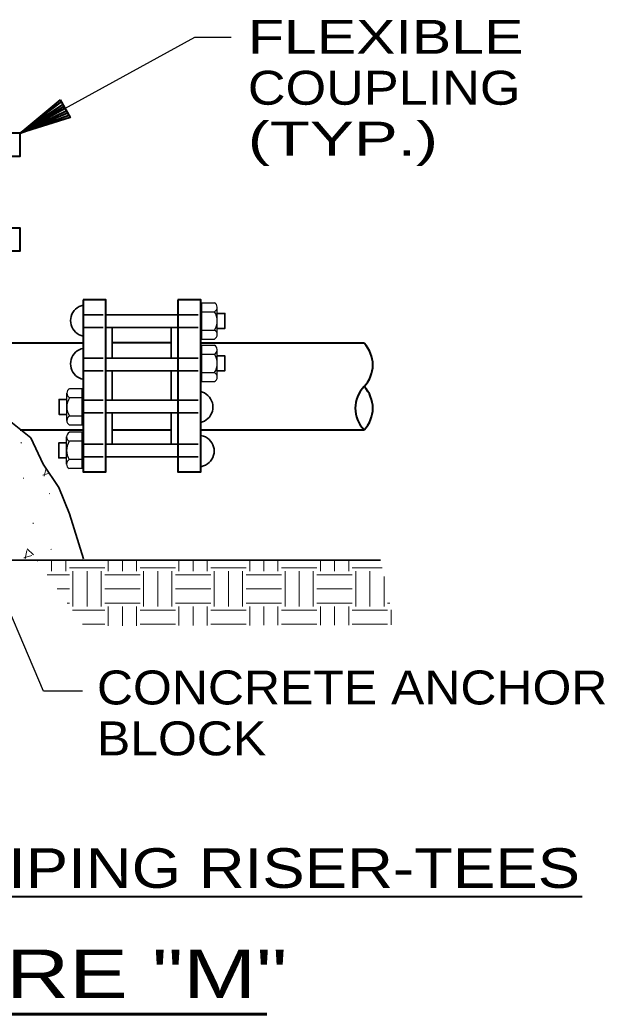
# Model space of a CAD drawing. Extents: x 55 to 190, y 198 to 264.
# Drawn here: x 96.19 to 100.57, y 222.57 to 230.01 of the extents above; entities that cross this region are included whole.
import ezdxf
from ezdxf.enums import TextEntityAlignment as Align

# ---------------------------------------------------------------- set-up
doc = ezdxf.new("R2010")
doc.units = 0
doc.header["$LTSCALE"] = 0.1
doc.linetypes.add('SHORT_DASHED', pattern=[2.7, 1.5, -1.2])
doc.layers.add('2', color=7, linetype='Continuous', lineweight=40)

msp = doc.modelspace()

# ---------------------------------------------------------------- linework, layer by layer
at = {"layer": '2'}
for p, q in [((96.1973, 229.1653), (96.5053, 229.3992)), ((96.1973, 229.1653), (96.5158, 229.3807)), ((96.1973, 229.1653), (96.5235, 229.3656)), ((96.5325, 229.35), (96.1973, 229.1653)), ((96.1973, 229.1653), (96.5415, 229.3331)), ((96.1973, 229.1653), (96.5595, 229.3003)), ((95.8777, 227.5972), (96.6672, 227.5972)), ((97.3257, 227.5977), (96.8852, 227.5977)), ((97.5483, 227.5972), (98.7696, 227.5972)), ((96.197, 226.9465), (96.6672, 226.9465)), ((96.8852, 226.9465), (97.3257, 226.9465)), ((97.5483, 226.9463), (98.7696, 226.9463)), ((91.6756, 223.4514), (100.4002, 223.4514))]:
    msp.add_line(p, q, dxfattribs=at)
at = {"layer": '2', "lineweight": 25}
for p, q in [((97.5551, 227.6241), (97.5551, 227.8969)), ((97.5551, 227.8969), (97.6493, 227.8969)), ((97.6708, 227.6585), (97.6708, 227.8628)), ((97.5551, 227.8289), (97.6501, 227.8289)), ((97.5551, 227.6919), (97.6501, 227.6919)), ((97.5551, 227.6241), (97.6501, 227.6241)), ((97.5551, 227.3064), (97.5551, 227.5792)), ((97.5551, 227.5792), (97.6493, 227.5792)), ((97.5551, 227.5112), (97.6501, 227.5112)), ((97.6708, 227.3408), (97.6708, 227.545)), ((97.5551, 227.3741), (97.6501, 227.3741)), ((97.5551, 227.3064), (97.6501, 227.3064)), ((96.5455, 227.0148), (96.5455, 227.2191)), ((96.6611, 227.2532), (96.5669, 227.2532)), ((96.6611, 226.9804), (96.6611, 227.2532)), ((96.6611, 227.1852), (96.5661, 227.1852)), ((96.6611, 227.0481), (96.5661, 227.0481)), ((96.6611, 226.9804), (96.5661, 226.9804)), ((96.5436, 226.6891), (96.5436, 226.8934)), ((96.6593, 226.9275), (96.5651, 226.9275)), ((96.6593, 226.6547), (96.6593, 226.9275)), ((96.6593, 226.8595), (96.5643, 226.8595)), ((96.6593, 226.7224), (96.5643, 226.7224)), ((96.6593, 226.6547), (96.5643, 226.6547))]:
    msp.add_line(p, q, dxfattribs=at)
at = {"layer": '2', "linetype": 'SHORT_DASHED', "lineweight": 35}
for p, q in [((96.6677, 227.8059), (96.8386, 227.8059)), ((97.3773, 227.8059), (97.5483, 227.8059)), ((96.6677, 227.7115), (96.8386, 227.7115)), ((97.3773, 227.7115), (97.5483, 227.7115)), ((96.6677, 227.4826), (96.8386, 227.4826)), ((97.3773, 227.4826), (97.5483, 227.4826)), ((96.6677, 227.3881), (96.8386, 227.3881)), ((97.3773, 227.3881), (97.5483, 227.3881)), ((96.6677, 227.1675), (96.8386, 227.1675)), ((97.3773, 227.1675), (97.5483, 227.1675)), ((96.6677, 227.073), (96.8386, 227.073)), ((97.3773, 227.073), (97.5483, 227.073)), ((96.6677, 226.8381), (96.8386, 226.8381)), ((97.3773, 226.8381), (97.5483, 226.8381)), ((96.6677, 226.7436), (96.8386, 226.7436)), ((97.3773, 226.7436), (97.5483, 226.7436))]:
    msp.add_line(p, q, dxfattribs=at)
at = {"layer": '2', "lineweight": 35}
for p, q in [((96.8381, 227.8059), (97.3773, 227.8059)), ((96.8381, 227.7115), (97.3773, 227.7115)), ((96.8836, 227.7115), (96.8836, 227.4834)), ((97.326, 227.4834), (97.326, 227.7115)), ((96.8381, 227.4826), (97.3773, 227.4826)), ((96.8381, 227.3881), (97.3773, 227.3881)), ((96.8836, 227.3884), (96.8836, 227.1672)), ((97.326, 227.1672), (97.326, 227.3884)), ((97.3773, 227.1675), (96.8381, 227.1675)), ((97.3773, 227.073), (96.8381, 227.073)), ((96.8836, 227.0722), (96.8836, 226.8381)), ((97.326, 226.8381), (97.326, 227.0722)), ((97.3773, 226.8381), (96.8381, 226.8381)), ((97.3773, 226.7436), (96.8381, 226.7436)), ((92.4897, 225.9702), (98.8931, 225.9702))]:
    msp.add_line(p, q, dxfattribs=at)
at = {"layer": '2', "lineweight": 13}
for p, q in [((96.206, 226.8463), (96.2021, 226.8497)), ((96.3658, 226.6063), (96.4061, 226.6184)), ((96.3873, 226.6481), (96.3759, 226.5986)), ((96.2208, 226.5801), (96.2222, 226.5854)), ((96.419, 226.469), (96.414, 226.4674)), ((96.2949, 226.248), (96.2936, 226.243)), ((96.2232, 225.9872), (96.2838, 226.0057)), ((96.2473, 226.0419), (96.233, 225.98)), ((96.2952, 226.0107), (96.2486, 226.0538)), ((96.4256, 226.0491), (96.4317, 226.0509)), ((96.3262, 225.9633), (96.3262, 225.9737)), ((96.432, 225.8866), (96.432, 225.9737)), ((96.5378, 225.8866), (96.5378, 225.9737)), ((96.8553, 225.8866), (96.8553, 225.9737)), ((96.9612, 225.8866), (96.9612, 225.9737)), ((97.067, 225.8866), (97.067, 225.9737)), ((97.3845, 225.8866), (97.3845, 225.9737)), ((97.4903, 225.8866), (97.4903, 225.9737)), ((97.5962, 225.8866), (97.5962, 225.9737)), ((97.9137, 225.8866), (97.9137, 225.9737)), ((98.0195, 225.8866), (98.0195, 225.9737)), ((98.1253, 225.8866), (98.1253, 225.9737)), ((98.4428, 225.8866), (98.4428, 225.9737)), ((98.5487, 225.8866), (98.5487, 225.9737)), ((98.6545, 225.8866), (98.6545, 225.9737)), ((96.3994, 225.8602), (96.5643, 225.8602)), ((96.5643, 225.9131), (96.8288, 225.9131)), ((96.5907, 225.622), (96.5907, 225.8866)), ((96.6966, 225.622), (96.6966, 225.8866)), ((96.8024, 225.622), (96.8024, 225.8866)), ((96.8288, 225.8602), (97.0934, 225.8602)), ((97.0934, 225.9131), (97.358, 225.9131)), ((97.1199, 225.622), (97.1199, 225.8866)), ((97.2257, 225.622), (97.2257, 225.8866)), ((97.3316, 225.622), (97.3316, 225.8866)), ((97.358, 225.8602), (97.6226, 225.8602)), ((97.6226, 225.9131), (97.8872, 225.9131)), ((97.6491, 225.622), (97.6491, 225.8866)), ((97.7549, 225.622), (97.7549, 225.8866)), ((97.8607, 225.622), (97.8607, 225.8866)), ((97.8872, 225.8602), (98.1518, 225.8602)), ((98.1518, 225.9131), (98.4164, 225.9131)), ((98.1782, 225.622), (98.1782, 225.8866)), ((98.2841, 225.622), (98.2841, 225.8866)), ((98.3899, 225.622), (98.3899, 225.8866)), ((98.4164, 225.8602), (98.6809, 225.8602)), ((98.6809, 225.9131), (98.9053, 225.9131)), ((98.7074, 225.622), (98.7074, 225.8866)), ((98.8132, 225.622), (98.8132, 225.8866)), ((98.9191, 225.622), (98.9191, 225.8475)), ((96.4743, 225.7543), (96.5643, 225.7543)), ((96.8288, 225.7543), (97.0934, 225.7543)), ((97.358, 225.7543), (97.6226, 225.7543)), ((97.8872, 225.7543), (98.1518, 225.7543)), ((98.4164, 225.7543), (98.6809, 225.7543)), ((96.5492, 225.6485), (96.5643, 225.6485)), ((96.8288, 225.6485), (97.0934, 225.6485)), ((97.358, 225.6485), (97.6226, 225.6485)), ((97.8872, 225.6485), (98.1518, 225.6485)), ((98.4164, 225.6485), (98.6809, 225.6485)), ((98.9455, 225.6485), (98.9611, 225.6485)), ((96.5868, 225.5956), (96.8288, 225.5956)), ((96.8553, 225.4786), (96.8553, 225.622)), ((96.9612, 225.4789), (96.9612, 225.622)), ((97.067, 225.4794), (97.067, 225.622)), ((97.0934, 225.5956), (97.358, 225.5956)), ((97.3845, 225.4802), (97.3845, 225.622)), ((97.4903, 225.4805), (97.4903, 225.622)), ((97.5962, 225.481), (97.5962, 225.622)), ((97.6226, 225.5956), (97.8872, 225.5956)), ((97.9137, 225.4818), (97.9137, 225.622)), ((98.0195, 225.4821), (98.0195, 225.622)), ((98.1253, 225.4826), (98.1253, 225.622)), ((98.1518, 225.5956), (98.4164, 225.5956)), ((98.4428, 225.4834), (98.4428, 225.622)), ((98.5487, 225.4837), (98.5487, 225.622)), ((98.6545, 225.4842), (98.6545, 225.622)), ((98.6809, 225.5956), (98.9455, 225.5956)), ((98.972, 225.485), (98.972, 225.5969)), ((96.6619, 225.4897), (96.8288, 225.4897)), ((97.0934, 225.4897), (97.358, 225.4897)), ((97.6226, 225.4897), (97.8872, 225.4897)), ((98.1518, 225.4897), (98.4164, 225.4897)), ((98.6809, 225.4897), (98.9455, 225.4897))]:
    msp.add_line(p, q, dxfattribs=at)
at = {"layer": '2', "lineweight": 60}
msp.add_line((94.3928, 222.5722), (98.043, 222.5722), dxfattribs=at)
at = {"layer": '2', "lineweight": 25}
for points in [[(97.7742, 229.881), (97.5006, 229.881), (96.1973, 229.1653)], [(96.6627, 224.9902), (96.3719, 224.9902), (95.9615, 225.9477)]]:
    msp.add_lwpolyline(points, dxfattribs=at)
at = {"layer": '2'}
for points in [[(96.4957, 229.4162), (96.5693, 229.282), (96.1973, 229.1653)], [(96.4957, 229.4162), (96.1973, 229.1653), (96.5508, 229.3167)]]:
    msp.add_lwpolyline(points, dxfattribs=at)
for points in [[(94.9104, 228.9944), (96.1973, 228.9944), (96.1973, 229.1653), (94.9104, 229.1653)], [(94.9104, 228.2843), (96.1973, 228.2843), (96.1973, 228.4552), (94.9104, 228.4552)], [(96.6672, 227.9183), (96.6672, 226.6314), (96.8381, 226.6314), (96.8381, 227.9183)], [(97.3773, 227.9183), (97.3773, 226.6314), (97.5483, 226.6314), (97.5483, 227.9183)]]:
    msp.add_lwpolyline(points, close=True, dxfattribs=at)
at = {"layer": '2', "lineweight": 35}
for points in [[(96.6672, 227.8784), (96.6524, 227.8744), (96.6376, 227.8678), (96.6238, 227.8596), (96.6111, 227.8493), (96.6, 227.8377), (96.5907, 227.8244), (96.5833, 227.8099), (96.5778, 227.7948), (96.5746, 227.7789), (96.5735, 227.7628), (96.5746, 227.7466), (96.5778, 227.7308), (96.5833, 227.7154), (96.5907, 227.7011), (96.6, 227.6879), (96.6111, 227.6763), (96.6238, 227.6659), (96.6376, 227.6575), (96.6524, 227.6511), (96.6672, 227.6472)], [(97.6713, 227.8167), (97.7287, 227.8167), (97.7287, 227.7048), (97.6713, 227.7048)], [(96.6672, 227.5551), (96.6524, 227.5511), (96.6376, 227.5445), (96.6238, 227.5363), (96.6111, 227.526), (96.6, 227.5143), (96.5907, 227.5011), (96.5833, 227.4866), (96.5778, 227.4715), (96.5746, 227.4556), (96.5735, 227.4394), (96.5746, 227.4233), (96.5778, 227.4074), (96.5833, 227.3921), (96.5907, 227.3778), (96.6, 227.3646), (96.6111, 227.3529), (96.6238, 227.3426), (96.6376, 227.3342), (96.6524, 227.3278), (96.6672, 227.3238)], [(97.6713, 227.499), (97.7287, 227.499), (97.7287, 227.3871), (97.6713, 227.3871)], [(96.6712, 225.9787), (96.5667, 226.3155), (96.4852, 226.5132), (96.369, 226.6875), (96.2761, 226.8852), (96.1018, 227.0246), (95.7996, 227.1873), (95.5324, 227.1873), (95.3231, 227.1987), (95.1138, 227.1291), (94.8932, 227.0246), (94.7188, 226.8153), (94.5794, 226.5714), (94.4632, 226.3272), (94.3891, 225.9702)], [(97.5483, 227.0013), (97.5599, 227.0045), (97.5747, 227.0108), (97.5887, 227.0193), (97.6012, 227.0296), (97.6123, 227.0413), (97.6215, 227.0545), (97.629, 227.0688), (97.6345, 227.0841), (97.6377, 227.1), (97.639, 227.1161), (97.6377, 227.1323), (97.6345, 227.1482), (97.629, 227.1635), (97.6215, 227.1778), (97.6123, 227.191), (97.6012, 227.2027), (97.5887, 227.213), (97.5747, 227.2212), (97.5599, 227.2278), (97.5483, 227.231)], [(96.545, 227.173), (96.4875, 227.173), (96.4875, 227.0611), (96.545, 227.0611)], [(97.5483, 226.6695), (97.5692, 226.6751), (97.584, 226.6814), (97.5977, 226.6899), (97.6104, 226.7002), (97.6213, 226.7118), (97.6308, 226.7251), (97.6382, 226.7394), (97.6438, 226.7547), (97.647, 226.7706), (97.648, 226.7867), (97.647, 226.8029), (97.6438, 226.8188), (97.6382, 226.8338), (97.6308, 226.8484), (97.6213, 226.8616), (97.6104, 226.8733), (97.5977, 226.8836), (97.584, 226.8918), (97.5692, 226.8984), (97.5483, 226.9039)], [(96.5431, 226.8473), (96.4857, 226.8473), (96.4857, 226.7354), (96.5431, 226.7354)]]:
    msp.add_lwpolyline(points, dxfattribs=at)
at = {"layer": '2', "lineweight": 25}
for centre, radius, start, end in [((97.6324, 227.8626), 0.0382, 298.1609, 63.21731), ((97.5447, 227.7603), 0.126, 327.05703, 32.99384), ((97.6326, 227.6581), 0.0382, 297.96581, 62.1123), ((97.6324, 227.5449), 0.0382, 298.1609, 63.21731), ((97.5447, 227.4426), 0.126, 327.05703, 32.99384), ((97.6326, 227.3403), 0.0382, 297.96581, 62.1123), ((96.5839, 227.2189), 0.0382, 116.78269, 241.8391), ((96.6715, 227.1166), 0.126, 147.00616, 212.94297), ((96.5836, 227.0143), 0.0382, 117.8877, 242.03419), ((96.582, 226.8932), 0.0382, 116.78269, 241.8391), ((96.6697, 226.7909), 0.126, 147.00616, 212.94297), ((96.5818, 226.6886), 0.0382, 117.8877, 242.03419)]:
    msp.add_arc(centre, radius, start, end, dxfattribs=at)
at = {"layer": '2'}
for centre, start, end in [((98.6019, 227.4313), 315.9775, 44.02119), ((98.9372, 227.1073), 135.9775, 224.02119), ((98.6019, 227.1073), 315.97881, 44.0225)]:
    msp.add_arc(centre, 0.2331, start, end, dxfattribs=at)

# ---------------------------------------------------------------- texts
for s, width, p in [('FLEXIBLE', 1.3, (97.8999, 229.7596)), ('COUPLING', 1.15, (97.8999, 229.3786)), ('(TYP.)', 1.45, (97.8999, 228.9976)), ('CONCRETE ANCHOR', 1.1, (96.7709, 224.8899)), ('BLOCK', 1.1, (96.7709, 224.5089))]:
    msp.add_text(s, height=0.254, dxfattribs=dict(at, width=width)).set_placement(p)
for s, height, width, p in [('UNDERGROUND PIPING RISER-TEES', 0.2963, 1.2, (96.1193, 223.5173)), ('FIGURE "M"', 0.3633, 1.35, (96.3596, 222.6923))]:
    msp.add_text(s, height=height, dxfattribs=dict(at, width=width)).set_placement(p, align=Align.CENTER)

doc.saveas('drawing.dxf')
